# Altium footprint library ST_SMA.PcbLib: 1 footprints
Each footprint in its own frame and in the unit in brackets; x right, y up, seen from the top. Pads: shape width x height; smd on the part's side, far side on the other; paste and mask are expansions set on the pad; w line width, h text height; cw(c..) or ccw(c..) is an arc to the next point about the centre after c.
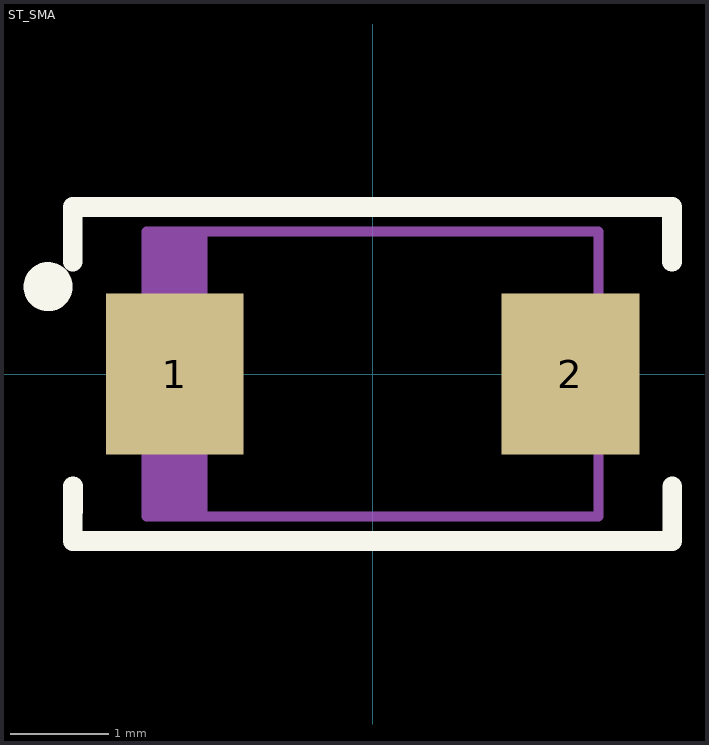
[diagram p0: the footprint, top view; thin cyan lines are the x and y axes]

## ST_SMA [mm]
height 2.65
pads (2):
  rect 1.4x1.64 smd: 1(-2.015,0) 2(2.015,0)
Top Overlay:
  circle w0.25: c-3.302,0.889 r0.125
  lines w0.2: -3.05,1.143 -3.05,1.7 3.05,1.7 ; -3.048,-1.143 -3.05,-1.7 3.05,-1.7 3.05,-1.145 ; 3.048,1.143 3.048,1.698
Mechanical 13:
  rectangle: -2.3,-1.45 -1.681,1.45
  lines w0.1: -2.3,-1.45 2.3,-1.45 2.3,1.45 -2.3,1.45 -2.3,-1.45
3D body "CAPM3216X18N.step": height 2.65, standoff 0, extent -2.52,-1.45 2.52,1.45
